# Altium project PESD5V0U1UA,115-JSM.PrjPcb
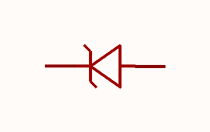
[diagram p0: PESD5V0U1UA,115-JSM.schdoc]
1 sheet, 1 parts. Net scope: global (net labels, ports and power ports of the same name join across sheets).

## Sheet PESD5V0U1UA,115-JSM.schdoc
size 127 x 101 mm

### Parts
D?  pesd5v0u1ua,115-jsm  [SOD-323_L1.7-W1.3-LS2.6-RD-1]  (value not drawn)

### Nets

Not connected (* = marked no-connect by the designer): D? 1(K) 2(A)

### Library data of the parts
D? = pesd5v0u1ua,115-jsm: 极性:-;反向截止电压(Vrwm):5V;钳位电压:20V;峰值脉冲电流(Ipp):4A@8/20us;峰值脉冲功率(Ppp):80W@8/20us;击穿电压(VBR):7.5V;; Manufacturer: JSMSEMI(杰盛微); AddInBom: yes; ModelId: eba151483b2844ffacda3a6d97308fa1; ModelTransform: 100.394,49.2125,0,0,0,0,0,0,0; Reverse Stand-Off Voltage (Vrwm): 5V; Clamping Voltage: 20V; Voltage - Breakdown: 7.5V; Reverse Leakage Current (Ir): 200nA; Number of Channels: 单路; level of protection: IEC 61000-4-2; Type: ESD; Junction Capacitance: 0.5pF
